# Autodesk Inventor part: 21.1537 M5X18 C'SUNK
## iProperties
Created: 2006-12
Part Number: 21.1537 M5X18 C'SUNK
Material: Steel, Mild
Description: Hexagon socket countersunk head cap screws
Document SubType Name: Modeling
Standard: DIN 7991
Designer: Andy Moles
Standards Organization: DIN
Language: en-US
Size Designation: M5x16
Categories: <MemberInstance Version="R10.0.0"><Categories><Category DisplayName="Fasteners" InternalName="e4da775c-781d-43d5-af7c-5136215cf5a6" Mnemonic="FSTN"><Category Di
Density: 7.86 g/cm^3
Author: Andy Moles
Revision Number: 1
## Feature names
1. Revolution1
2. Extrusion1
3. Fillet1
4. Chamfer1
